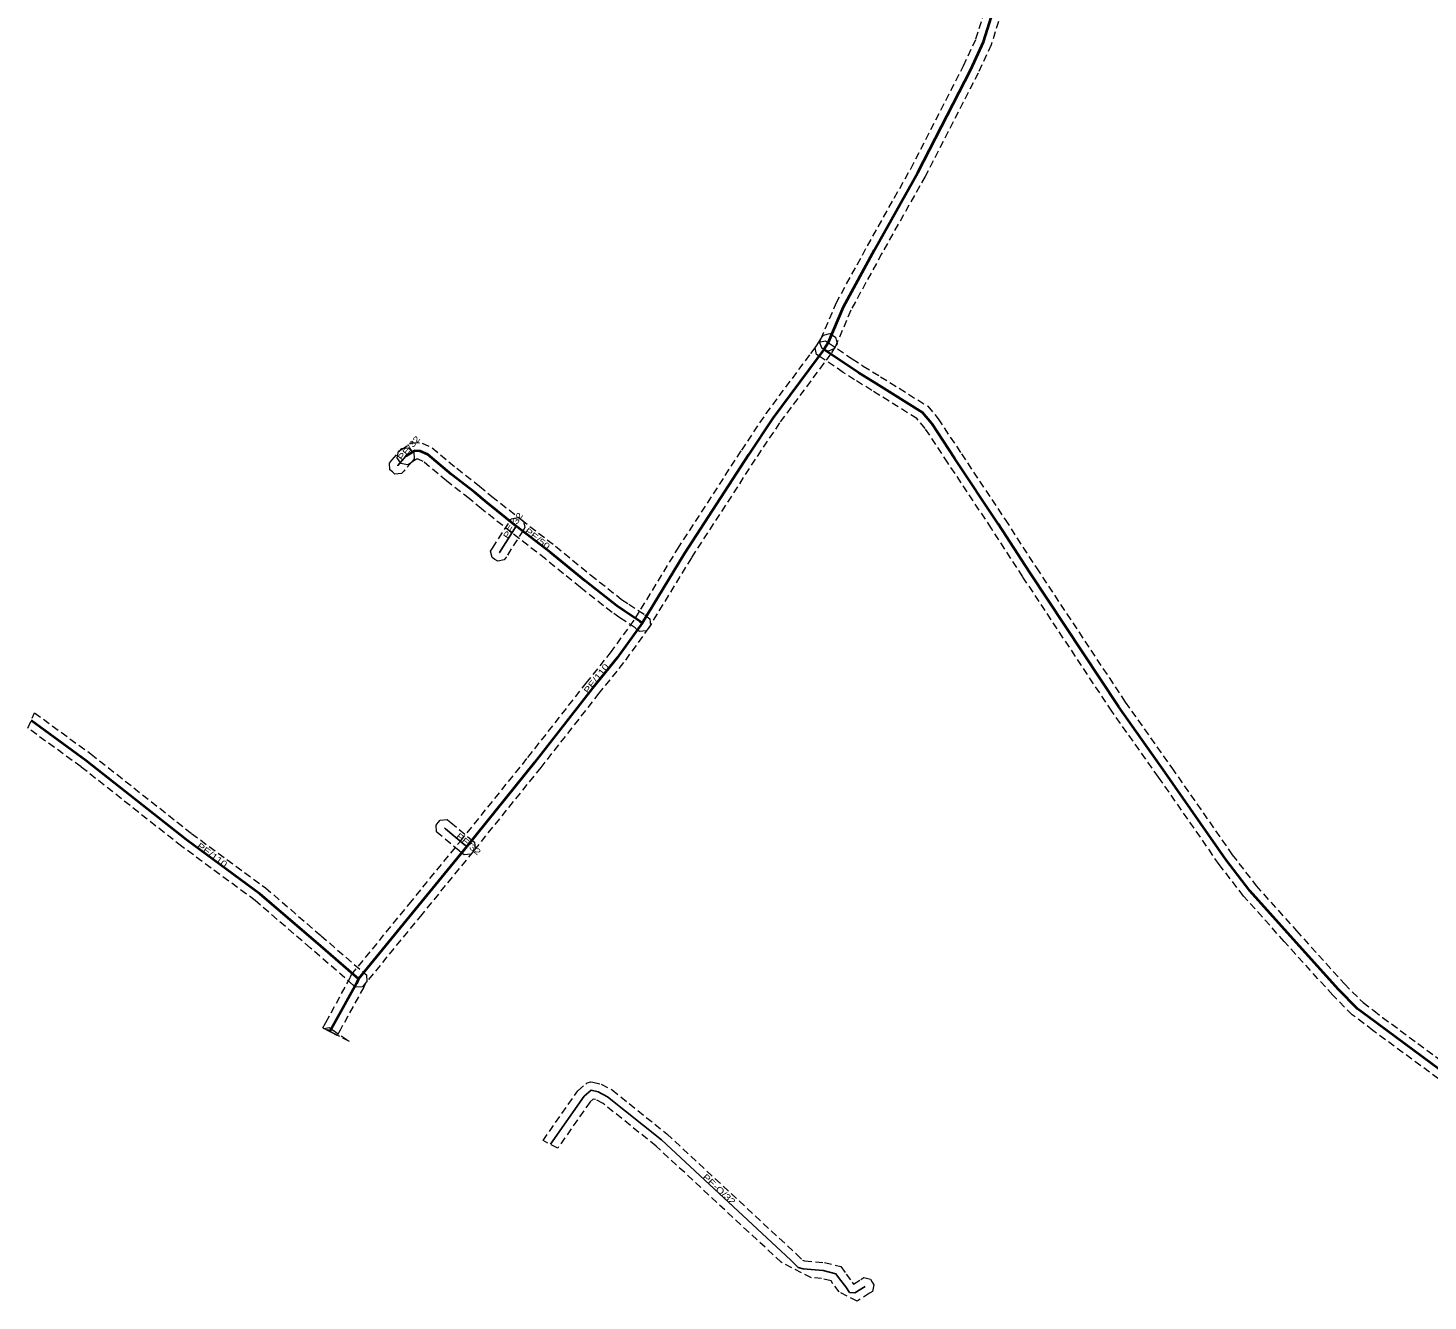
# Model space of a CAD drawing. Extents: x -601345 to -601001, y -1004225 to -1003815.
# Drawn here: x -601345.1 to -601172.9, y -1004176.9 to -1004020.2 of the extents above; entities that cross this region are included whole.
import ezdxf

# ---------------------------------------------------------------- set-up
doc = ezdxf.new("R2010")
doc.units = 0
doc.header["$LTSCALE"] = 0.3
doc.linetypes.add('MEDIUM_DASHED', pattern=[4.5, 3, -1.5])
doc.layers.add('1', color=7, linetype='MEDIUM_DASHED', lineweight=13)
doc.layers.add('24', color=7, linetype='Continuous', lineweight=25)
doc.layers.add('30', color=7, linetype='Continuous')

msp = doc.modelspace()

# ---------------------------------------------------------------- linework, layer by layer
at = {"layer": '1'}
for points in [[(-601224.896, -1004016.86), (-601226.606, -1004022.312), (-601228.221, -1004025.779), (-601234.729, -1004038.503), (-601240.075, -1004048.014), (-601243.869, -1004054.976), (-601245.699, -1004059.291), (-601245.861, -1004059.672), (-601246.63, -1004059.983), (-601247.011, -1004059.821), (-601247.392, -1004059.659), (-601247.703, -1004058.89), (-601247.541, -1004058.509), (-601245.671, -1004054.104), (-601241.825, -1004047.046), (-601236.491, -1004037.557), (-601230.019, -1004024.901), (-601228.474, -1004021.588), (-601226.804, -1004016.26)], [(-601169.407, -1004151.127), (-601179.652, -1004143.578), (-601180.754, -1004142.727), (-601182.179, -1004141.666), (-601184.587, -1004139.217), (-601190.543, -1004132.649), (-601195.55, -1004127.049), (-601198.557, -1004123.141), (-601206.018, -1004112.405), (-601211.765, -1004104.305), (-601222.717, -1004087.758), (-601226.566, -1004081.808), (-601231.933, -1004073.733), (-601234.723, -1004069.518), (-601235.736, -1004068.303), (-601241.267, -1004064.84), (-601243.407, -1004063.524), (-601244.793, -1004062.613), (-601247.747, -1004060.63), (-601248.091, -1004060.399), (-601248.251, -1004059.587), (-601248.02, -1004059.243), (-601247.789, -1004058.899), (-601246.977, -1004058.739), (-601246.633, -1004058.97), (-601243.687, -1004060.947), (-601242.333, -1004061.836), (-601240.213, -1004063.14), (-601234.404, -1004066.777), (-601233.117, -1004068.322), (-601230.267, -1004072.627), (-601224.894, -1004080.712), (-601221.043, -1004086.662), (-601210.115, -1004103.175), (-601204.382, -1004111.255), (-601196.943, -1004121.959), (-601194.01, -1004125.771), (-601189.057, -1004131.311), (-601183.133, -1004137.843), (-601180.861, -1004140.154), (-601179.546, -1004141.133), (-601178.448, -1004141.982), (-601168.713, -1004149.153)]]:
    msp.add_lwpolyline(points, dxfattribs=at)
for points in [[(-601307.048, -1004144.182), (-601308.831, -1004143.271), (-601308.445, -1004142.585), (-601305.585, -1004137.352), (-601305.286, -1004136.697), (-601298.205, -1004128.038), (-601291.897, -1004120.3), (-601283.583, -1004109.978), (-601276.413, -1004100.838), (-601273.416, -1004097.114), (-601270.384, -1004092.897), (-601265.177, -1004084.358), (-601257.295, -1004072.19), (-601254.277, -1004067.683), (-601248.796, -1004060.308), (-601248.018, -1004059.238), (-601247.465, -1004058.365), (-601247.243, -1004058.015), (-601246.435, -1004057.833), (-601246.085, -1004058.055), (-601245.735, -1004058.277), (-601245.553, -1004059.085), (-601245.775, -1004059.435), (-601246.362, -1004060.362), (-601247.184, -1004061.492), (-601252.643, -1004068.837), (-601255.625, -1004073.29), (-601263.483, -1004085.422), (-601268.716, -1004094.003), (-601271.824, -1004098.326), (-601274.847, -1004102.082), (-601282.017, -1004111.222), (-601290.343, -1004121.56), (-601296.655, -1004129.302), (-601303.574, -1004137.763), (-601303.795, -1004138.248), (-601306.695, -1004143.555)], [(-601269.851, -1004094.49), (-601270.175, -1004094.231), (-601270.389, -1004094.059), (-601272.297, -1004092.801), (-601273.242, -1004092.157), (-601277.127, -1004089.089), (-601281.433, -1004085.562), (-601285.636, -1004082.307), (-601289.291, -1004079.416), (-601290.808, -1004078.148), (-601293.608, -1004075.968), (-601296.46, -1004073.582), (-601297.103, -1004073.285), (-601297.294, -1004073.271), (-601298.053, -1004073.767), (-601298.4, -1004073.994), (-601299.21, -1004073.824), (-601299.437, -1004073.477), (-601299.664, -1004073.13), (-601299.494, -1004072.32), (-601299.147, -1004072.093), (-601297.826, -1004071.229), (-601296.597, -1004071.315), (-601295.38, -1004071.878), (-601292.352, -1004074.412), (-601289.552, -1004076.592), (-601288.029, -1004077.864), (-601284.404, -1004080.733), (-601280.187, -1004083.998), (-601275.873, -1004087.531), (-601272.058, -1004090.543), (-601271.183, -1004091.139), (-601269.211, -1004092.441), (-601268.925, -1004092.669), (-601268.601, -1004092.928), (-601268.51, -1004093.751), (-601268.769, -1004094.075), (-601269.028, -1004094.399)], [(-601300.636, -1004073.762), (-601300.366, -1004073.448), (-601300.347, -1004073.427), (-601299.358, -1004072.278), (-601299.088, -1004071.964), (-601298.262, -1004071.902), (-601297.948, -1004072.172), (-601297.634, -1004072.442), (-601297.572, -1004073.268), (-601297.842, -1004073.582), (-601298.833, -1004074.733), (-601298.852, -1004074.756), (-601299.123, -1004075.069), (-601299.949, -1004075.129), (-601300.263, -1004074.859), (-601300.576, -1004074.588)], [(-601283.954, -1004081.709), (-601284.177, -1004082.058), (-601286.248, -1004085.3), (-601286.27, -1004085.333), (-601286.495, -1004085.681), (-601287.304, -1004085.856), (-601287.652, -1004085.631), (-601288, -1004085.406), (-601288.175, -1004084.597), (-601287.95, -1004084.249), (-601287.932, -1004084.22), (-601285.863, -1004080.982), (-601285.64, -1004080.633), (-601284.831, -1004080.454), (-601284.482, -1004080.677), (-601284.133, -1004080.9)], [(-601345.088, -1004106.393), (-601344.287, -1004104.502), (-601337.355, -1004109.553), (-601324.963, -1004119.345), (-601315.886, -1004126.027), (-601309.037, -1004131.923), (-601303.776, -1004136.474), (-601303.462, -1004136.745), (-601303.403, -1004137.571), (-601303.674, -1004137.884), (-601303.945, -1004138.198), (-601304.771, -1004138.257), (-601305.084, -1004137.986), (-601310.343, -1004133.437), (-601317.134, -1004127.593), (-601326.177, -1004120.935), (-601338.565, -1004111.147)], [(-601291.421, -1004121.97), (-601291.745, -1004121.711), (-601292.053, -1004121.464), (-601294.361, -1004119.538), (-601294.504, -1004119.418), (-601294.822, -1004119.153), (-601294.897, -1004118.328), (-601294.632, -1004118.01), (-601294.367, -1004117.692), (-601293.542, -1004117.617), (-601293.224, -1004117.882), (-601293.079, -1004118.002), (-601290.787, -1004119.916), (-601290.495, -1004120.149), (-601290.171, -1004120.408), (-601290.08, -1004121.231), (-601290.339, -1004121.555), (-601290.598, -1004121.879)], [(-601307.677, -1004143.46), (-601305.542, -1004144.952), (-601308.69, -1004143.343), (-601308.017, -1004143.223)], [(-601307.525, -1004143.929), (-601307.523, -1004143.939), (-601308.369, -1004143.507), (-601308.218, -1004143.475), (-601307.872, -1004143.702)], [(-601275.944, -1004152.349), (-601279.929, -1004158.043), (-601281.727, -1004157.124), (-601277.436, -1004150.991), (-601276.468, -1004150.168), (-601276.289, -1004150.015), (-601275.831, -1004149.903), (-601275.601, -1004149.954), (-601274.583, -1004150.183), (-601273.23, -1004150.889), (-601266.515, -1004156.293), (-601250.56, -1004171.106), (-601249.811, -1004171.839), (-601249.555, -1004171.913), (-601247.122, -1004172.131), (-601245.098, -1004172.64), (-601244.454, -1004173.548), (-601243.698, -1004174.542), (-601243.528, -1004174.775), (-601242.617, -1004174.21), (-601242.265, -1004173.992), (-601241.458, -1004174.181), (-601241.24, -1004174.533), (-601241.022, -1004174.885), (-601241.211, -1004175.692), (-601241.563, -1004175.91), (-601243.103, -1004176.865), (-601245.298, -1004175.743), (-601245.302, -1004175.738), (-601246.066, -1004174.732), (-601246.302, -1004174.4), (-601247.458, -1004174.109), (-601248.717, -1004173.996), (-601252.433, -1004172.097), (-601267.825, -1004157.807), (-601274.33, -1004152.571), (-601275.277, -1004152.077), (-601275.552, -1004152.015)]]:
    msp.add_lwpolyline(points, close=True, dxfattribs=at)
at = {"layer": '24', "lineweight": 40}
for points in [[(-601246.62, -1004058.9), (-601244.77, -1004054.54), (-601240.95, -1004047.53), (-601235.61, -1004038.03), (-601229.12, -1004025.34), (-601227.54, -1004021.95), (-601225.85, -1004016.56)], [(-601246.62, -1004058.9), (-601247.19, -1004059.8), (-601247.99, -1004060.9), (-601253.46, -1004068.26), (-601256.46, -1004072.74), (-601264.33, -1004084.89), (-601269.55, -1004093.45), (-601272.62, -1004097.72), (-601275.63, -1004101.46), (-601282.8, -1004110.6), (-601291.12, -1004120.93), (-601297.43, -1004128.67), (-601304.43, -1004137.23), (-601304.69, -1004137.8), (-601307.57, -1004143.07), (-601307.939, -1004143.727)], [(-601169.06, -1004150.14), (-601179.05, -1004142.78), (-601180.15, -1004141.93), (-601181.52, -1004140.91), (-601183.86, -1004138.53), (-601189.8, -1004131.98), (-601194.78, -1004126.41), (-601197.75, -1004122.55), (-601205.2, -1004111.83), (-601210.94, -1004103.74), (-601221.88, -1004087.21), (-601225.73, -1004081.26), (-601231.1, -1004073.18), (-601233.92, -1004068.92), (-601235.07, -1004067.54), (-601240.74, -1004063.99), (-601242.87, -1004062.68), (-601244.24, -1004061.78), (-601247.19, -1004059.8)], [(-601269.55, -1004093.45), (-601269.8, -1004093.25), (-601271.74, -1004091.97), (-601272.65, -1004091.35), (-601276.5, -1004088.31), (-601280.81, -1004084.78), (-601285.02, -1004081.52), (-601288.66, -1004078.64), (-601290.18, -1004077.37), (-601292.98, -1004075.19), (-601295.92, -1004072.73), (-601296.85, -1004072.3), (-601297.56, -1004072.25), (-601298.6, -1004072.93)], [(-601304.43, -1004137.23), (-601309.69, -1004132.68), (-601316.51, -1004126.81), (-601325.57, -1004120.14), (-601337.96, -1004110.35), (-601344.687, -1004105.447)]]:
    msp.add_lwpolyline(points, dxfattribs=at)
at = {"layer": '24'}
for points in [[(-601299.609, -1004074.102), (-601299.59, -1004074.08), (-601298.6, -1004072.93)], [(-601285.02, -1004081.52), (-601287.09, -1004084.76), (-601287.11, -1004084.791)], [(-601291.12, -1004120.93), (-601291.42, -1004120.69), (-601293.72, -1004118.77), (-601293.864, -1004118.65)], [(-601242.09, -1004175.06), (-601243.38, -1004175.86), (-601244.01, -1004175.81), (-601244.5, -1004175.14), (-601245.26, -1004174.14), (-601245.7, -1004173.52), (-601247.29, -1004173.12), (-601249.74, -1004172.9), (-601250.33, -1004172.73), (-601251.25, -1004171.83), (-601267.17, -1004157.05), (-601273.78, -1004151.73), (-601274.93, -1004151.13), (-601275.82, -1004150.93), (-601276.69, -1004151.67), (-601280.828, -1004157.584)]]:
    msp.add_lwpolyline(points, dxfattribs=at)

# ---------------------------------------------------------------- texts
at = {"layer": '30', "width": 1.3}
for s, rotation, p in [('PE/32', 49.276, (-601299.105, -1004073.516)), ('PE/32', 57.426, (-601286.065, -1004083.155)), ('PE/50', 322.248, (-601284.046, -1004082.274)), ('PE/110', 51.887, (-601276.204, -1004102.192)), ('PE/32', 320.145, (-601292.494, -1004119.793)), ('PE/110', 323.639, (-601324.367, -1004121.026)), ('PE-O/32', 317.127, (-601262.162, -1004161.699))]:
    msp.add_text(s, height=0.75, rotation=rotation, dxfattribs=at).set_placement(p)

doc.saveas('drawing.dxf')
